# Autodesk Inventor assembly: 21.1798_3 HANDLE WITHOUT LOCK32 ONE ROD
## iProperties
Created: 2007-03
Part Number: 21.1798_3 HANDLE WITHOUT LOCK32 ONE ROD
Document SubType Name: Assembly
Designer: Andy Moles
Author: Andy Moles
